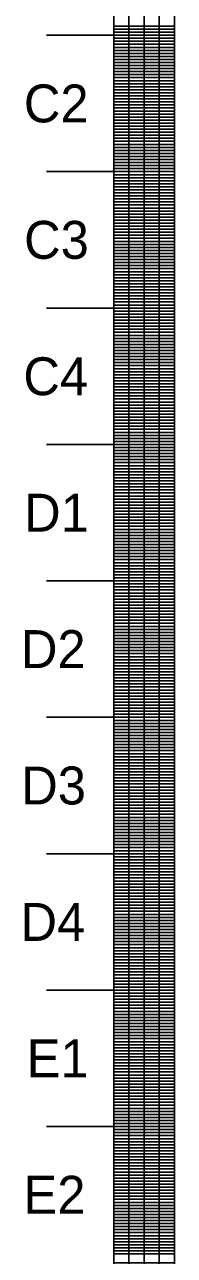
# Model space of a CAD drawing. Extents: x -124 to 80, y -10800 to 19.
# Drawn here: x -118 to 80, y -3230 to -1606 of the extents above; entities that cross this region are included whole.
import ezdxf

# ---------------------------------------------------------------- set-up
doc = ezdxf.new("R2010")
doc.units = 0
for name, color, linetype in [('Scratch_Level_1', 7, 'Continuous'), ('Scratch_Level_3', 7, 'Continuous'), ('Sheet Clip Boundary CELL', 7, 'Continuous')]:
    doc.layers.add(name, color=color, linetype=linetype)

msp = doc.modelspace()

# ---------------------------------------------------------------- linework, layer by layer
at = {"layer": 'Scratch_Level_1'}
for p, q in [((0, 0), (0, -6480)), ((20, 0), (20, -6480)), ((40, 0), (40, -6480)), ((60, 0), (60, -6480)), ((80, 0), (80, -6480)), ((0, -1620), (-88.8, -1620)), ((0, -1608), (80, -1608)), ((0, -1612), (80, -1612)), ((0, -1616), (80, -1616)), ((0, -1620), (80, -1620)), ((0, -1624), (80, -1624)), ((0, -1628), (80, -1628)), ((0, -1632), (80, -1632)), ((0, -1636), (80, -1636)), ((0, -1640), (80, -1640)), ((0, -1644), (80, -1644)), ((0, -1648), (80, -1648)), ((0, -1652), (80, -1652)), ((0, -1656), (80, -1656)), ((0, -1660), (80, -1660)), ((0, -1664), (80, -1664)), ((0, -1668), (80, -1668)), ((0, -1672), (80, -1672)), ((0, -1676), (80, -1676)), ((0, -1680), (80, -1680)), ((0, -1684), (80, -1684)), ((0, -1688), (80, -1688)), ((0, -1692), (80, -1692)), ((0, -1696), (80, -1696)), ((0, -1700), (80, -1700)), ((0, -1704), (80, -1704)), ((0, -1708), (80, -1708)), ((0, -1712), (80, -1712)), ((0, -1716), (80, -1716)), ((0, -1720), (80, -1720)), ((0, -1724), (80, -1724)), ((0, -1728), (80, -1728)), ((0, -1732), (80, -1732)), ((0, -1736), (80, -1736)), ((0, -1740), (80, -1740)), ((0, -1744), (80, -1744)), ((0, -1748), (80, -1748)), ((0, -1752), (80, -1752)), ((0, -1756), (80, -1756)), ((0, -1760), (80, -1760)), ((0, -1764), (80, -1764)), ((0, -1768), (80, -1768)), ((0, -1772), (80, -1772)), ((0, -1776), (80, -1776)), ((0, -1780), (80, -1780)), ((0, -1784), (80, -1784)), ((0, -1800), (-88.8, -1800)), ((0, -1788), (80, -1788)), ((0, -1792), (80, -1792)), ((0, -1796), (80, -1796)), ((0, -1800), (80, -1800)), ((0, -1804), (80, -1804)), ((0, -1808), (80, -1808)), ((0, -1812), (80, -1812)), ((0, -1816), (80, -1816)), ((0, -1820), (80, -1820)), ((0, -1824), (80, -1824)), ((0, -1828), (80, -1828)), ((0, -1832), (80, -1832)), ((0, -1836), (80, -1836)), ((0, -1840), (80, -1840)), ((0, -1844), (80, -1844)), ((0, -1848), (80, -1848)), ((0, -1852), (80, -1852)), ((0, -1856), (80, -1856)), ((0, -1860), (80, -1860)), ((0, -1864), (80, -1864)), ((0, -1868), (80, -1868)), ((0, -1872), (80, -1872)), ((0, -1876), (80, -1876)), ((0, -1880), (80, -1880)), ((0, -1884), (80, -1884)), ((0, -1888), (80, -1888)), ((0, -1892), (80, -1892)), ((0, -1896), (80, -1896)), ((0, -1900), (80, -1900)), ((0, -1904), (80, -1904)), ((0, -1908), (80, -1908)), ((0, -1912), (80, -1912)), ((0, -1916), (80, -1916)), ((0, -1920), (80, -1920)), ((0, -1924), (80, -1924)), ((0, -1928), (80, -1928)), ((0, -1932), (80, -1932)), ((0, -1936), (80, -1936)), ((0, -1940), (80, -1940)), ((0, -1944), (80, -1944)), ((0, -1948), (80, -1948)), ((0, -1952), (80, -1952)), ((0, -1956), (80, -1956)), ((0, -1960), (80, -1960)), ((0, -1964), (80, -1964)), ((0, -1980), (-88.8, -1980)), ((0, -1968), (80, -1968)), ((0, -1972), (80, -1972)), ((0, -1976), (80, -1976)), ((0, -1980), (80, -1980)), ((0, -1984), (80, -1984)), ((0, -1988), (80, -1988)), ((0, -1992), (80, -1992)), ((0, -1996), (80, -1996)), ((0, -2000), (80, -2000)), ((0, -2004), (80, -2004)), ((0, -2008), (80, -2008)), ((0, -2012), (80, -2012)), ((0, -2016), (80, -2016)), ((0, -2020), (80, -2020)), ((0, -2024), (80, -2024)), ((0, -2028), (80, -2028)), ((0, -2032), (80, -2032)), ((0, -2036), (80, -2036)), ((0, -2040), (80, -2040)), ((0, -2044), (80, -2044)), ((0, -2048), (80, -2048)), ((0, -2052), (80, -2052)), ((0, -2056), (80, -2056)), ((0, -2060), (80, -2060)), ((0, -2064), (80, -2064)), ((0, -2068), (80, -2068)), ((0, -2072), (80, -2072)), ((0, -2076), (80, -2076)), ((0, -2080), (80, -2080)), ((0, -2084), (80, -2084)), ((0, -2088), (80, -2088)), ((0, -2092), (80, -2092)), ((0, -2096), (80, -2096)), ((0, -2100), (80, -2100)), ((0, -2104), (80, -2104)), ((0, -2108), (80, -2108)), ((0, -2112), (80, -2112)), ((0, -2116), (80, -2116)), ((0, -2120), (80, -2120)), ((0, -2124), (80, -2124)), ((0, -2128), (80, -2128)), ((0, -2132), (80, -2132)), ((0, -2136), (80, -2136)), ((0, -2140), (80, -2140)), ((0, -2144), (80, -2144)), ((0, -2148), (80, -2148)), ((0, -2152), (80, -2152)), ((0, -2156), (80, -2156)), ((0, -2160), (-88.8, -2160)), ((0, -2160), (80, -2160)), ((0, -2164), (80, -2164)), ((0, -2168), (80, -2168)), ((0, -2172), (80, -2172)), ((0, -2176), (80, -2176)), ((0, -2180), (80, -2180)), ((0, -2184), (80, -2184)), ((0, -2188), (80, -2188)), ((0, -2192), (80, -2192)), ((0, -2196), (80, -2196)), ((0, -2200), (80, -2200)), ((0, -2204), (80, -2204)), ((0, -2208), (80, -2208)), ((0, -2212), (80, -2212)), ((0, -2216), (80, -2216)), ((0, -2220), (80, -2220)), ((0, -2224), (80, -2224)), ((0, -2228), (80, -2228)), ((0, -2232), (80, -2232)), ((0, -2236), (80, -2236)), ((0, -2240), (80, -2240)), ((0, -2244), (80, -2244)), ((0, -2248), (80, -2248)), ((0, -2252), (80, -2252)), ((0, -2256), (80, -2256)), ((0, -2260), (80, -2260)), ((0, -2264), (80, -2264)), ((0, -2268), (80, -2268)), ((0, -2272), (80, -2272)), ((0, -2276), (80, -2276)), ((0, -2280), (80, -2280)), ((0, -2284), (80, -2284)), ((0, -2288), (80, -2288)), ((0, -2292), (80, -2292)), ((0, -2296), (80, -2296)), ((0, -2300), (80, -2300)), ((0, -2304), (80, -2304)), ((0, -2308), (80, -2308)), ((0, -2312), (80, -2312)), ((0, -2316), (80, -2316)), ((0, -2320), (80, -2320)), ((0, -2324), (80, -2324)), ((0, -2328), (80, -2328)), ((0, -2332), (80, -2332)), ((0, -2336), (80, -2336)), ((0, -2340), (-88.8, -2340)), ((0, -2340), (80, -2340)), ((0, -2344), (80, -2344)), ((0, -2348), (80, -2348)), ((0, -2352), (80, -2352)), ((0, -2356), (80, -2356)), ((0, -2360), (80, -2360)), ((0, -2364), (80, -2364)), ((0, -2368), (80, -2368)), ((0, -2372), (80, -2372)), ((0, -2376), (80, -2376)), ((0, -2380), (80, -2380)), ((0, -2384), (80, -2384)), ((0, -2388), (80, -2388)), ((0, -2392), (80, -2392)), ((0, -2396), (80, -2396)), ((0, -2400), (80, -2400)), ((0, -2404), (80, -2404)), ((0, -2408), (80, -2408)), ((0, -2412), (80, -2412)), ((0, -2416), (80, -2416)), ((0, -2420), (80, -2420)), ((0, -2424), (80, -2424)), ((0, -2428), (80, -2428)), ((0, -2432), (80, -2432)), ((0, -2436), (80, -2436)), ((0, -2440), (80, -2440)), ((0, -2444), (80, -2444)), ((0, -2448), (80, -2448)), ((0, -2452), (80, -2452)), ((0, -2456), (80, -2456)), ((0, -2460), (80, -2460)), ((0, -2464), (80, -2464)), ((0, -2468), (80, -2468)), ((0, -2472), (80, -2472)), ((0, -2476), (80, -2476)), ((0, -2480), (80, -2480)), ((0, -2484), (80, -2484)), ((0, -2488), (80, -2488)), ((0, -2492), (80, -2492)), ((0, -2496), (80, -2496)), ((0, -2500), (80, -2500)), ((0, -2504), (80, -2504)), ((0, -2508), (80, -2508)), ((0, -2512), (80, -2512)), ((0, -2516), (80, -2516)), ((0, -2520), (-88.8, -2520)), ((0, -2520), (80, -2520)), ((0, -2524), (80, -2524)), ((0, -2528), (80, -2528)), ((0, -2532), (80, -2532)), ((0, -2536), (80, -2536)), ((0, -2540), (80, -2540)), ((0, -2544), (80, -2544)), ((0, -2548), (80, -2548)), ((0, -2552), (80, -2552)), ((0, -2556), (80, -2556)), ((0, -2560), (80, -2560)), ((0, -2564), (80, -2564)), ((0, -2568), (80, -2568)), ((0, -2572), (80, -2572)), ((0, -2576), (80, -2576)), ((0, -2580), (80, -2580)), ((0, -2584), (80, -2584)), ((0, -2588), (80, -2588)), ((0, -2592), (80, -2592)), ((0, -2596), (80, -2596)), ((0, -2600), (80, -2600)), ((0, -2604), (80, -2604)), ((0, -2608), (80, -2608)), ((0, -2612), (80, -2612)), ((0, -2616), (80, -2616)), ((0, -2620), (80, -2620)), ((0, -2624), (80, -2624)), ((0, -2628), (80, -2628)), ((0, -2632), (80, -2632)), ((0, -2636), (80, -2636)), ((0, -2640), (80, -2640)), ((0, -2644), (80, -2644)), ((0, -2648), (80, -2648)), ((0, -2652), (80, -2652)), ((0, -2656), (80, -2656)), ((0, -2660), (80, -2660)), ((0, -2664), (80, -2664)), ((0, -2668), (80, -2668)), ((0, -2672), (80, -2672)), ((0, -2676), (80, -2676)), ((0, -2680), (80, -2680)), ((0, -2684), (80, -2684)), ((0, -2688), (80, -2688)), ((0, -2692), (80, -2692)), ((0, -2700), (-88.8, -2700)), ((0, -2696), (80, -2696)), ((0, -2700), (80, -2700)), ((0, -2704), (80, -2704)), ((0, -2708), (80, -2708)), ((0, -2712), (80, -2712)), ((0, -2716), (80, -2716)), ((0, -2720), (80, -2720)), ((0, -2724), (80, -2724)), ((0, -2728), (80, -2728)), ((0, -2732), (80, -2732)), ((0, -2736), (80, -2736)), ((0, -2740), (80, -2740)), ((0, -2744), (80, -2744)), ((0, -2748), (80, -2748)), ((0, -2752), (80, -2752)), ((0, -2756), (80, -2756)), ((0, -2760), (80, -2760)), ((0, -2764), (80, -2764)), ((0, -2768), (80, -2768)), ((0, -2772), (80, -2772)), ((0, -2776), (80, -2776)), ((0, -2780), (80, -2780)), ((0, -2784), (80, -2784)), ((0, -2788), (80, -2788)), ((0, -2792), (80, -2792)), ((0, -2796), (80, -2796)), ((0, -2800), (80, -2800)), ((0, -2804), (80, -2804)), ((0, -2808), (80, -2808)), ((0, -2812), (80, -2812)), ((0, -2816), (80, -2816)), ((0, -2820), (80, -2820)), ((0, -2824), (80, -2824)), ((0, -2828), (80, -2828)), ((0, -2832), (80, -2832)), ((0, -2836), (80, -2836)), ((0, -2840), (80, -2840)), ((0, -2844), (80, -2844)), ((0, -2848), (80, -2848)), ((0, -2852), (80, -2852)), ((0, -2856), (80, -2856)), ((0, -2860), (80, -2860)), ((0, -2864), (80, -2864)), ((0, -2868), (80, -2868)), ((0, -2872), (80, -2872)), ((0, -2880), (-88.8, -2880)), ((0, -2876), (80, -2876)), ((0, -2880), (80, -2880)), ((0, -2884), (80, -2884)), ((0, -2888), (80, -2888)), ((0, -2892), (80, -2892)), ((0, -2896), (80, -2896)), ((0, -2900), (80, -2900)), ((0, -2904), (80, -2904)), ((0, -2908), (80, -2908)), ((0, -2912), (80, -2912)), ((0, -2916), (80, -2916)), ((0, -2920), (80, -2920)), ((0, -2924), (80, -2924)), ((0, -2928), (80, -2928)), ((0, -2932), (80, -2932)), ((0, -2936), (80, -2936)), ((0, -2940), (80, -2940)), ((0, -2944), (80, -2944)), ((0, -2948), (80, -2948)), ((0, -2952), (80, -2952)), ((0, -2956), (80, -2956)), ((0, -2960), (80, -2960)), ((0, -2964), (80, -2964)), ((0, -2968), (80, -2968)), ((0, -2972), (80, -2972)), ((0, -2976), (80, -2976)), ((0, -2980), (80, -2980)), ((0, -2984), (80, -2984)), ((0, -2988), (80, -2988)), ((0, -2992), (80, -2992)), ((0, -2996), (80, -2996)), ((0, -3000), (80, -3000)), ((0, -3004), (80, -3004)), ((0, -3008), (80, -3008)), ((0, -3012), (80, -3012)), ((0, -3016), (80, -3016)), ((0, -3020), (80, -3020)), ((0, -3024), (80, -3024)), ((0, -3028), (80, -3028)), ((0, -3032), (80, -3032)), ((0, -3036), (80, -3036)), ((0, -3040), (80, -3040)), ((0, -3044), (80, -3044)), ((0, -3048), (80, -3048)), ((0, -3052), (80, -3052)), ((0, -3060), (-88.8, -3060)), ((0, -3056), (80, -3056)), ((0, -3060), (80, -3060)), ((0, -3064), (80, -3064)), ((0, -3068), (80, -3068)), ((0, -3072), (80, -3072)), ((0, -3076), (80, -3076)), ((0, -3080), (80, -3080)), ((0, -3084), (80, -3084)), ((0, -3088), (80, -3088)), ((0, -3092), (80, -3092)), ((0, -3096), (80, -3096)), ((0, -3100), (80, -3100)), ((0, -3104), (80, -3104)), ((0, -3108), (80, -3108)), ((0, -3112), (80, -3112)), ((0, -3116), (80, -3116)), ((0, -3120), (80, -3120)), ((0, -3124), (80, -3124)), ((0, -3128), (80, -3128)), ((0, -3132), (80, -3132)), ((0, -3136), (80, -3136)), ((0, -3140), (80, -3140)), ((0, -3144), (80, -3144)), ((0, -3148), (80, -3148)), ((0, -3152), (80, -3152)), ((0, -3156), (80, -3156)), ((0, -3160), (80, -3160)), ((0, -3164), (80, -3164)), ((0, -3168), (80, -3168)), ((0, -3172), (80, -3172)), ((0, -3176), (80, -3176)), ((0, -3180), (80, -3180)), ((0, -3184), (80, -3184)), ((0, -3188), (80, -3188)), ((0, -3192), (80, -3192)), ((0, -3196), (80, -3196)), ((0, -3200), (80, -3200)), ((0, -3204), (80, -3204)), ((0, -3208), (80, -3208)), ((0, -3212), (80, -3212)), ((0, -3216), (80, -3216)), ((0, -3220), (80, -3220)), ((0, -3224), (80, -3224)), ((0, -3228), (80, -3228))]:
    msp.add_line(p, q, dxfattribs=at)
at = {"layer": 'Sheet Clip Boundary CELL'}
for points in [[(0, -1440), (80, -1440), (80, -1620), (0, -1620)], [(0, -1620), (80, -1620), (80, -1800), (0, -1800)], [(0, -1800), (80, -1800), (80, -1980), (0, -1980)], [(0, -1980), (80, -1980), (80, -2160), (0, -2160)], [(0, -2160), (80, -2160), (80, -2340), (0, -2340)], [(0, -2340), (80, -2340), (80, -2520), (0, -2520)], [(0, -2520), (80, -2520), (80, -2700), (0, -2700)], [(0, -2700), (80, -2700), (80, -2880), (0, -2880)], [(0, -2880), (80, -2880), (80, -3060), (0, -3060)], [(0, -3060), (80, -3060), (80, -3240), (0, -3240)]]:
    msp.add_lwpolyline(points, close=True, dxfattribs=at)

# ---------------------------------------------------------------- texts
at = {"layer": 'Scratch_Level_3'}
for s, p in [('C2', (-118.7, -1735)), ('C3', (-118.4, -1915)), ('C4', (-119.4, -2095)), ('D1', (-118.4, -2275)), ('D2', (-122.6, -2455)), ('D3', (-122.2, -2635)), ('D4', (-123.2, -2815)), ('E1', (-115, -2995)), ('E2', (-119.1, -3175))]:
    msp.add_text(s, height=50, dxfattribs=at).set_placement(p)

doc.saveas('drawing.dxf')
